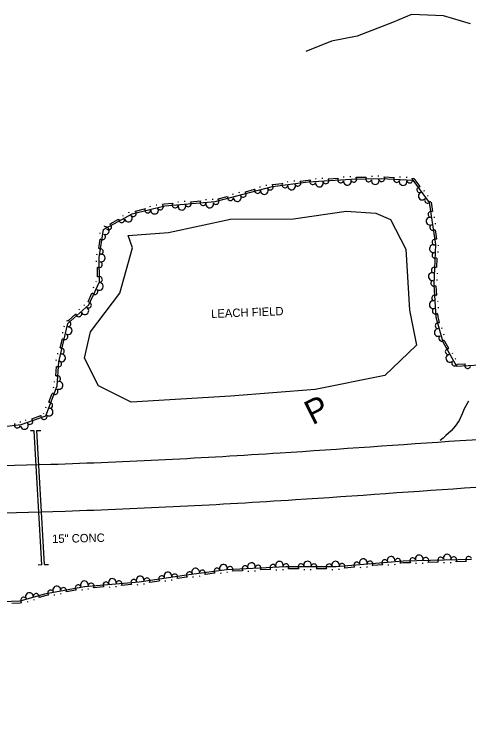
# Model space of a CAD drawing. Extents: x 2030130 to 2036320, y 723205 to 762423.
# Drawn here: x 2034480.3 to 2034679.9, y 760944.6 to 761261.2 of the extents above; entities that cross this region are included whole.
import ezdxf

# ---------------------------------------------------------------- set-up
doc = ezdxf.new("R2010")
doc.units = 0
for name, color, linetype in [('Draft_Station Labels Major', 7, 'Continuous'), ('Draft_Station Tics Major', 7, 'Continuous'), ('Draft_Station Tics Minor', 7, 'Continuous'), ('Exist Terrain Model Ground Surface', 7, 'Continuous'), ('Old_Level_26', 7, 'Continuous'), ('Old_Level_28', 7, 'Continuous'), ('Prop Alignment Horizontal', 7, 'Continuous'), ('Prop Horizontal Alignment Ramp', 7, 'Continuous')]:
    doc.layers.add(name, color=color, linetype=linetype)

msp = doc.modelspace()

# ---------------------------------------------------------------- linework, layer by layer
at = {"layer": 'Draft_Station Labels Major'}
msp.add_lwpolyline([(2034679.89, 761091.18), (2034677.96, 761087.85), (2034677.11, 761085.59), (2034675.8, 761082.69), (2034673.92, 761080.27), (2034672.2, 761078.17), (2034669.95, 761076.06), (2034668.68, 761074.99), (2034667.33, 761073.98)], dxfattribs=at)
for points in [[(2034092.04, 760960.15), (2034128.02, 760985.27), (2034167.72, 761010.14), (2034207.02, 761028.78), (2034238.75, 761041.08), (2034290.36, 761053.26), (2034339.84, 761057.27), (2034410.92, 761061), (2034496.35, 761063.49), (2034597.04, 761068.5), (2034676.22, 761073.92), (2034760.74, 761078.95), (2034860.07, 761085.08), (2034928.36, 761090.57)], [(2034112.77, 760944.64), (2034147.71, 760969.04), (2034185.56, 760992.74), (2034222.61, 761010.31), (2034251.75, 761021.61), (2034299.66, 761032.92), (2034346.78, 761036.74), (2034417.19, 761040.43), (2034502.59, 761042.92), (2034603.78, 761047.95), (2034683.1, 761053.38), (2034767.53, 761058.4), (2034867.13, 761064.56), (2034935.91, 761070.08)]]:
    msp.add_spline(points, degree=3, dxfattribs=at)
at = {"layer": 'Draft_Station Tics Major'}
for points in [[(2034624.85, 761189.79), (2034625.26, 761189.82)], [(2034627.72, 761189.97), (2034628.13, 761189.99)], [(2034630.65, 761189.64), (2034634.75, 761189.73)], [(2034637.2, 761190.19), (2034637.61, 761190.2)], [(2034640.07, 761190.25), (2034640.48, 761190.26)], [(2034643, 761189.79), (2034647.1, 761189.59)], [(2034649.58, 761189.87), (2034649.99, 761189.85)], [(2034652.44, 761189.73), (2034652.85, 761189.71)], [(2034471.87, 761079.61), (2034483.29, 761080.92), (2034494.08, 761084.77), (2034499.1, 761097.9), (2034499.82, 761108.48), (2034503.85, 761125.31), (2034512.99, 761133.6), (2034517.67, 761143.67), (2034517.64, 761154.38), (2034519.52, 761166.65), (2034532.14, 761173.61), (2034546.36, 761177.15), (2034568.55, 761178.93), (2034593.75, 761185.62), (2034609.44, 761187.61), (2034628.34, 761188.77), (2034641.47, 761189.05), (2034655.41, 761188.35), (2034662.58, 761178.61), (2034665.28, 761160.1), (2034664.63, 761142.5), (2034665.49, 761128.14), (2034668.55, 761117.31), (2034674.52, 761106.6), (2034684.82, 761107.2)], [(2034593.81, 761186.45), (2034597.88, 761186.97)], [(2034600.27, 761187.69), (2034600.68, 761187.74)], [(2034603.12, 761188.05), (2034603.52, 761188.1)], [(2034606.02, 761188), (2034609.36, 761188.43), (2034610.14, 761188.48)], [(2034612.57, 761189.04), (2034612.98, 761189.06)], [(2034615.44, 761189.21), (2034615.85, 761189.24)], [(2034618.33, 761188.98), (2034622.42, 761189.23)], [(2034655.29, 761189.17), (2034655.84, 761189.15), (2034658.41, 761185.66)], [(2034581.81, 761183.3), (2034585.77, 761184.35)], [(2034588.05, 761185.38), (2034588.44, 761185.48)], [(2034590.82, 761186.11), (2034591.22, 761186.22)], [(2034660.2, 761183.92), (2034660.44, 761183.59)], [(2034567.22, 761180.06), (2034567.63, 761180.09)], [(2034569.92, 761180.14), (2034573.88, 761181.19)], [(2034576.15, 761182.22), (2034576.55, 761182.33)], [(2034578.93, 761182.96), (2034579.32, 761183.06)], [(2034661.9, 761181.61), (2034662.14, 761181.28)], [(2034539.8, 761176.79), (2034540.2, 761176.89)], [(2034542.59, 761177.48), (2034542.98, 761177.58)], [(2034545.47, 761177.78), (2034546.23, 761177.96), (2034549.67, 761178.24)], [(2034552.09, 761178.85), (2034552.5, 761178.88)], [(2034554.95, 761179.07), (2034555.36, 761179.11)], [(2034557.85, 761178.9), (2034561.94, 761179.22)], [(2034564.36, 761179.83), (2034564.76, 761179.86)], [(2034663.4, 761178.68), (2034663.99, 761174.62)], [(2034530.47, 761174.09), (2034530.83, 761174.29)], [(2034533.53, 761174.8), (2034537.51, 761175.79)], [(2034522.41, 761169.18), (2034526, 761171.16)], [(2034527.95, 761172.71), (2034528.31, 761172.91)], [(2034664.75, 761172.25), (2034664.81, 761171.84)], [(2034519.7, 761168.15), (2034520.05, 761168.35)], [(2034665.17, 761169.41), (2034665.23, 761169)], [(2034518, 761164.86), (2034518.07, 761165.27)], [(2034665.18, 761166.51), (2034665.77, 761162.45)], [(2034517.41, 761158.31), (2034518.04, 761162.37)], [(2034666.5, 761159.85), (2034666.49, 761159.44)], [(2034516.57, 761155.54), (2034516.63, 761155.95)], [(2034666.4, 761156.98), (2034666.38, 761156.57)], [(2034516.42, 761152.49), (2034516.41, 761152.9)], [(2034665.88, 761154.12), (2034665.73, 761150.03)], [(2034516.84, 761145.93), (2034516.83, 761150.03)], [(2034666.05, 761147.55), (2034666.03, 761147.14)], [(2034516.3, 761143.64), (2034516.47, 761144.01)], [(2034665.94, 761144.68), (2034665.93, 761144.27)], [(2034515.09, 761141.03), (2034515.26, 761141.41)], [(2034665.49, 761141.91), (2034665.73, 761137.82)], [(2034512.69, 761134.91), (2034514.42, 761138.63)], [(2034510.82, 761133.3), (2034511.12, 761133.57)], [(2034666.29, 761135.39), (2034666.31, 761134.98)], [(2034666.46, 761132.52), (2034666.49, 761132.11)], [(2034504.11, 761126.65), (2034507.15, 761129.41)], [(2034508.7, 761131.37), (2034509, 761131.64)], [(2034666.23, 761129.63), (2034666.31, 761128.27), (2034667, 761125.8)], [(2034502.24, 761123.87), (2034502.34, 761124.27)], [(2034668.06, 761123.55), (2034668.18, 761123.15)], [(2034501.57, 761121.08), (2034501.67, 761121.48)], [(2034668.84, 761120.78), (2034668.96, 761120.39)], [(2034500.44, 761114.6), (2034501.4, 761118.59)], [(2034669.23, 761117.91), (2034669.31, 761117.62), (2034671.07, 761114.47)], [(2034499.38, 761111.91), (2034499.47, 761112.31)], [(2034672.63, 761112.52), (2034672.82, 761112.16)], [(2034498.71, 761109.12), (2034498.8, 761109.51)], [(2034674.02, 761110.01), (2034674.22, 761109.65)], [(2034674.99, 761107.44), (2034678.21, 761107.63)], [(2034498.58, 761102.35), (2034498.86, 761106.44)], [(2034497.98, 761099.51), (2034498, 761099.92)], [(2034495.51, 761090.81), (2034496.98, 761094.64)], [(2034497.47, 761097.09), (2034497.62, 761097.47)], [(2034494.1, 761088.28), (2034494.25, 761088.66)], [(2034493.08, 761085.6), (2034493.23, 761085.98)], [(2034482.72, 761082.09), (2034483.13, 761082.14)], [(2034485.17, 761082.9), (2034485.56, 761083.04)], [(2034488.01, 761083.48), (2034491.88, 761084.86)], [(2034681.11, 761021.64), (2034651.1, 761020.91), (2034621.77, 761018.33), (2034599.57, 761018.39), (2034573.57, 761017.13), (2034555.89, 761014.68), (2034535.13, 761011.71), (2034511.12, 761009.67), (2034493.55, 761006.4), (2034482.78, 761003.3), (2034468.01, 761002.71)], [(2034641.92, 761019.28), (2034637.83, 761018.92)], [(2034644.81, 761019.12), (2034644.4, 761019.09)], [(2034647.67, 761019.37), (2034647.26, 761019.34)], [(2034654.13, 761020.16), (2034651.15, 761020.09), (2034650.09, 761020)], [(2034657.01, 761019.82), (2034656.6, 761019.81)], [(2034659.88, 761019.89), (2034659.47, 761019.88)], [(2034666.43, 761020.46), (2034662.33, 761020.36)], [(2034669.31, 761020.12), (2034668.9, 761020.11)], [(2034672.18, 761020.19), (2034671.77, 761020.18)], [(2034678.73, 761020.76), (2034674.63, 761020.66)], [(2034568.3, 761015.57), (2034564.24, 761015.01)], [(2034571.2, 761015.56), (2034570.79, 761015.51)], [(2034573.93, 761015.92), (2034573.69, 761015.91), (2034573.63, 761015.9)], [(2034580.47, 761016.65), (2034576.37, 761016.45)], [(2034583.35, 761016.38), (2034582.95, 761016.36)], [(2034586.22, 761016.52), (2034585.82, 761016.49)], [(2034592.76, 761017.24), (2034588.66, 761017.04)], [(2034595.64, 761016.97), (2034595.23, 761016.95)], [(2034598.51, 761017.11), (2034598.1, 761017.09)], [(2034605.01, 761017.56), (2034600.91, 761017.57)], [(2034607.88, 761017.14), (2034607.47, 761017.14)], [(2034610.75, 761017.13), (2034610.34, 761017.13)], [(2034617.31, 761017.52), (2034613.21, 761017.53)], [(2034620.18, 761017.1), (2034619.77, 761017.11)], [(2034623.16, 761017.22), (2034622.75, 761017.18)], [(2034629.66, 761018.2), (2034625.58, 761017.84)], [(2034632.56, 761018.04), (2034632.15, 761018.01)], [(2034635.42, 761018.3), (2034635.01, 761018.26)], [(2034543.94, 761012.14), (2034539.88, 761011.56)], [(2034546.83, 761012.14), (2034546.43, 761012.08)], [(2034549.68, 761012.55), (2034549.27, 761012.49)], [(2034556.11, 761013.88), (2034556, 761013.87), (2034552.06, 761013.3)], [(2034559.01, 761013.87), (2034558.61, 761013.81)], [(2034561.86, 761014.26), (2034561.45, 761014.21)], [(2034519.43, 761009.55), (2034515.34, 761009.21)], [(2034522.32, 761009.39), (2034521.91, 761009.35)], [(2034525.18, 761009.63), (2034524.77, 761009.59)], [(2034531.69, 761010.59), (2034527.6, 761010.25)], [(2034534.58, 761010.43), (2034534.17, 761010.39)], [(2034537.5, 761010.8), (2034537.09, 761010.74)], [(2034495.21, 761005.87), (2034493.74, 761005.6), (2034491.31, 761004.9)], [(2034498.1, 761005.99), (2034497.7, 761005.92)], [(2034500.93, 761006.52), (2034500.53, 761006.45)], [(2034507.3, 761008.13), (2034503.27, 761007.38)], [(2034510.2, 761008.25), (2034509.8, 761008.18)], [(2034512.92, 761008.59), (2034512.52, 761008.56)], [(2034486.3, 761003.03), (2034485.91, 761002.92)], [(2034489.06, 761003.83), (2034488.66, 761003.71)], [(2034483.43, 761002.63), (2034482.91, 761002.48), (2034479.15, 761002.33)]]:
    msp.add_lwpolyline(points, dxfattribs=at)
for centre, radius, start, end in [((2034629.43, 761188.8), 1.3, 199.6379, 40.4345), ((2034635.99, 761188.93), 1.3, 141.9714, 342.768), ((2034641.73, 761189.03), 1.3, 195.5529, 36.3495), ((2034648.29, 761188.7), 1.3, 137.8864, 338.683), ((2034592.72, 761185.35), 1.3, 213.2969, 54.0935), ((2034599.2, 761186.31), 1.3, 148.017, 348.8135), ((2034602.15, 761185.86), 1.69, 173.2122, 21.2847), ((2034604.9, 761187.04), 1.3, 205.6834, 46.48), ((2034611.42, 761187.73), 1.3, 144.2763, 345.0728), ((2034614.34, 761187.09), 1.69, 169.4715, 17.544), ((2034617.15, 761188.09), 1.3, 201.9427, 42.7393), ((2034623.7, 761188.49), 1.3, 144.2763, 345.0728), ((2034626.62, 761187.84), 1.69, 169.4715, 17.544), ((2034638.88, 761188.17), 1.69, 167.1667, 15.2392), ((2034651.11, 761187.74), 1.69, 163.0817, 11.1542), ((2034654.02, 761188.42), 1.3, 195.5529, 36.3495), ((2034580.83, 761182.19), 1.3, 213.2969, 54.0935), ((2034587.17, 761183.87), 1.3, 155.6305, 356.427), ((2034590.16, 761183.82), 1.69, 180.8257, 28.8982), ((2034658.48, 761184.19), 1.3, 87.1312, 287.9278), ((2034568.94, 761179.03), 1.3, 213.2969, 54.0935), ((2034575.28, 761180.72), 1.3, 155.6305, 356.427), ((2034578.27, 761180.66), 1.69, 180.8257, 28.8982), ((2034659.52, 761181.39), 1.69, 112.3265, 320.399), ((2034661.88, 761179.56), 1.3, 144.7977, 345.5943), ((2034544.47, 761176.68), 1.3, 212.4059, 53.2024), ((2034550.96, 761177.52), 1.3, 145.3478, 346.1444), ((2034553.89, 761176.93), 1.69, 170.5431, 18.6156), ((2034556.69, 761177.98), 1.3, 203.0143, 43.8108), ((2034563.23, 761178.5), 1.3, 145.3478, 346.1444), ((2034566.15, 761177.92), 1.69, 170.5431, 18.6156), ((2034532.54, 761173.71), 1.3, 212.4059, 53.2024), ((2034538.9, 761175.3), 1.3, 154.7394, 355.536), ((2034541.89, 761175.19), 1.69, 179.9347, 28.0072), ((2034663.36, 761173.29), 1.3, 59.0741, 259.8706), ((2034527.47, 761171.04), 1.3, 169.6673, 10.4638), ((2034530.38, 761171.7), 1.69, 194.8625, 42.935), ((2034662.96, 761170.33), 1.69, 84.2693, 292.3418), ((2034520.28, 761166.17), 1.69, 247.2311, 95.3036), ((2034521.73, 761167.86), 1.3, 227.3337, 68.1303), ((2034664.19, 761167.6), 1.3, 116.7405, 317.5371), ((2034519.03, 761163.46), 1.3, 222.0359, 62.8324), ((2034665.13, 761161.11), 1.3, 59.0741, 259.8706), ((2034518.04, 761156.97), 1.3, 279.7023, 120.4989), ((2034664.39, 761158.28), 1.69, 73.8366, 281.9091), ((2034518.46, 761154.14), 1.69, 256.1172, 104.1897), ((2034665.11, 761155.38), 1.3, 106.3078, 307.1044), ((2034517.65, 761151.26), 1.3, 230.9219, 71.7185), ((2034664.86, 761148.83), 1.3, 48.6414, 249.4379), ((2034517.67, 761144.7), 1.3, 288.5884, 129.385), ((2034663.94, 761145.99), 1.69, 73.8366, 281.9091), ((2034517.64, 761141.66), 1.69, 231.02, 79.0925), ((2034664.65, 761143.09), 1.3, 106.3078, 307.1044), ((2034515.68, 761139.4), 1.3, 205.8248, 46.6213), ((2034664.99, 761136.54), 1.3, 54.2155, 255.012), ((2034512.86, 761133.49), 1.3, 240.6735, 81.4701), ((2034664.34, 761133.62), 1.69, 79.4108, 287.4832), ((2034508.61, 761129.63), 1.3, 183.0071, 23.8036), ((2034511.29, 761130.95), 1.69, 208.2023, 56.2748), ((2034665.33, 761130.81), 1.3, 111.8819, 312.6785), ((2034503.82, 761125.18), 1.3, 274.9519, 115.7485), ((2034503.95, 761122.2), 1.69, 242.4807, 90.5532), ((2034666.54, 761121.41), 1.69, 91.7072, 299.7797), ((2034666.55, 761124.4), 1.3, 66.5119, 267.3085), ((2034502.48, 761119.6), 1.3, 217.2854, 58.082), ((2034668.11, 761118.87), 1.3, 124.1784, 324.975), ((2034500.95, 761113.21), 1.3, 274.9519, 115.7485), ((2034670.95, 761113), 1.3, 79.9169, 280.7134), ((2034501.08, 761110.23), 1.69, 242.4807, 90.5532), ((2034671.63, 761110.09), 1.69, 105.1122, 313.1846), ((2034499.76, 761107.61), 1.3, 226.8916, 67.6882), ((2034673.75, 761107.98), 1.3, 137.5833, 338.3799), ((2034679.49, 761106.89), 1.3, 144.1103, 344.9069), ((2034499.32, 761101.06), 1.3, 284.5581, 125.3546), ((2034499.94, 761098.14), 1.69, 252.0869, 100.1594), ((2034498.18, 761095.5), 1.3, 209.8445, 50.6411), ((2034495.84, 761089.37), 1.3, 267.511, 108.3076), ((2034495.58, 761086.39), 1.69, 235.0398, 83.1123), ((2034487.13, 761082.29), 1.3, 218.0761, 58.8727), ((2034493.31, 761084.5), 1.3, 160.4096, 1.2062), ((2034481.64, 761080.73), 1.3, 147.2942, 348.0908), ((2034484.7, 761080.55), 1.69, 185.6049, 33.6774), ((2034633.6, 761020.19), 1.69, 350.9916, 199.0641), ((2034645.86, 761021.27), 1.69, 350.9916, 199.0641), ((2034648.79, 761020.71), 1.3, 325.7963, 166.5929), ((2034655.34, 761021.01), 1.3, 19.8252, 220.6218), ((2034658.19, 761021.9), 1.69, 347.354, 195.4265), ((2034661.08, 761021.15), 1.3, 322.1588, 162.9553), ((2034667.64, 761021.31), 1.3, 19.8252, 220.6218), ((2034670.49, 761022.2), 1.69, 347.354, 195.4265), ((2034673.38, 761021.45), 1.3, 322.1588, 162.9553), ((2034679.94, 761021.61), 1.3, 19.8252, 220.6218), ((2034572.13, 761017.76), 1.69, 353.8728, 201.9453), ((2034575.1, 761017.21), 1.3, 323.5381, 164.3347), ((2034581.66, 761017.53), 1.3, 21.2046, 222.0011), ((2034584.49, 761018.48), 1.69, 348.7334, 196.8059), ((2034587.39, 761017.8), 1.3, 323.5381, 164.3347), ((2034593.95, 761018.12), 1.3, 21.2046, 222.0011), ((2034596.77, 761019.08), 1.69, 348.7334, 196.8059), ((2034599.68, 761018.39), 1.3, 320.6098, 161.4063), ((2034606.24, 761018.37), 1.3, 18.2762, 219.0728), ((2034609.12, 761019.19), 1.69, 345.8051, 193.8775), ((2034611.98, 761018.36), 1.3, 320.6098, 161.4063), ((2034618.55, 761018.34), 1.3, 18.2762, 219.0728), ((2034621.42, 761019.15), 1.69, 345.8051, 193.8775), ((2034624.28, 761018.55), 1.3, 325.7963, 166.5929), ((2034630.81, 761019.13), 1.3, 23.4628, 224.2593), ((2034636.53, 761019.63), 1.3, 325.7963, 166.5929), ((2034643.07, 761020.2), 1.3, 23.4628, 224.2593), ((2034547.76, 761014.34), 1.69, 354.1094, 202.1819), ((2034557.22, 761014.86), 1.3, 26.344, 227.1406), ((2034559.95, 761016.07), 1.69, 353.8728, 201.9453), ((2034562.9, 761015.65), 1.3, 328.6775, 169.4741), ((2034569.4, 761016.56), 1.3, 26.344, 227.1406), ((2034511.12, 761010.5), 1.69, 350.804, 198.8765), ((2034523.38, 761011.53), 1.69, 350.804, 198.8765), ((2034526.31, 761010.96), 1.3, 325.6087, 166.4053), ((2034532.84, 761011.51), 1.3, 23.2752, 224.0718), ((2034535.58, 761012.6), 1.69, 354.1094, 202.1819), ((2034538.54, 761012.19), 1.3, 328.9141, 169.7107), ((2034545.04, 761013.12), 1.3, 26.5806, 227.3772), ((2034550.72, 761013.94), 1.3, 328.9141, 169.7107), ((2034498.94, 761008.24), 1.69, 356.527, 204.5995), ((2034501.91, 761007.96), 1.3, 331.3318, 172.1283), ((2034508.36, 761009.16), 1.3, 28.9982, 229.7948), ((2034514.05, 761009.92), 1.3, 325.6087, 166.4053), ((2034520.58, 761010.47), 1.3, 23.2752, 224.0718), ((2034486.92, 761005.34), 1.69, 2.0082, 210.0807), ((2034489.9, 761005.35), 1.3, 336.813, 177.6095), ((2034496.27, 761006.9), 1.3, 28.9982, 229.7948), ((2034484.38, 761003.76), 1.3, 34.4794, 235.276)]:
    msp.add_arc(centre, radius, start, end, dxfattribs=at)
at = {"layer": 'Draft_Station Tics Minor'}
for p, q in [((2034489, 761078.22), (2034487.36, 761078.12)), ((2034490.23, 761078.29), (2034491.87, 761078.38)), ((2034492.37, 761019.28), (2034490.73, 761019.19)), ((2034493.6, 761019.35), (2034495.24, 761019.45))]:
    msp.add_line(p, q, dxfattribs=at)
for points in [[(2034492.37, 761019.28), (2034489, 761078.22)], [(2034493.6, 761019.35), (2034490.23, 761078.29)]]:
    msp.add_lwpolyline(points, dxfattribs=at)
at = {"layer": 'Exist Terrain Model Ground Surface'}
msp.add_lwpolyline([(2034530.3, 761164.01), (2034548.08, 761165.38), (2034575.33, 761171.17), (2034602.89, 761171.35), (2034626.1, 761174.68), (2034639.16, 761173.85), (2034645.62, 761171.1), (2034652.27, 761158.07), (2034653.88, 761131.16), (2034656.97, 761115.89), (2034643.06, 761102.48), (2034612.54, 761096.32), (2034575.33, 761093.37), (2034531.59, 761090.84), (2034517.31, 761098.01), (2034511.09, 761110.1), (2034513.74, 761121.71), (2034526.58, 761138.64), (2034532.25, 761158.58)], close=True, dxfattribs=at)
at = {"layer": 'Prop Alignment Horizontal'}
msp.add_lwpolyline([(2034680.79, 761257.12), (2034668.83, 761260.56), (2034654.75, 761261.24), (2034646.43, 761257.73), (2034630.93, 761251.61), (2034619.71, 761249.49), (2034608.33, 761244.95)], dxfattribs=at)

# ---------------------------------------------------------------- texts
at = {"layer": 'Old_Level_26'}
msp.add_text('15" CONC', height=3.691, rotation=1.2938, dxfattribs=at).set_placement((2034496.93, 761028.85))
at = {"layer": 'Old_Level_28'}
msp.add_text('LEACH FIELD', height=3.6909, rotation=2.2266, dxfattribs=at).set_placement((2034566.84, 761127.79))
at = {"layer": 'Prop Horizontal Alignment Ramp'}
msp.add_text('P', height=10.66, rotation=26.3279, dxfattribs=at).set_placement((2034611.24, 761080.56))

doc.saveas('drawing.dxf')
